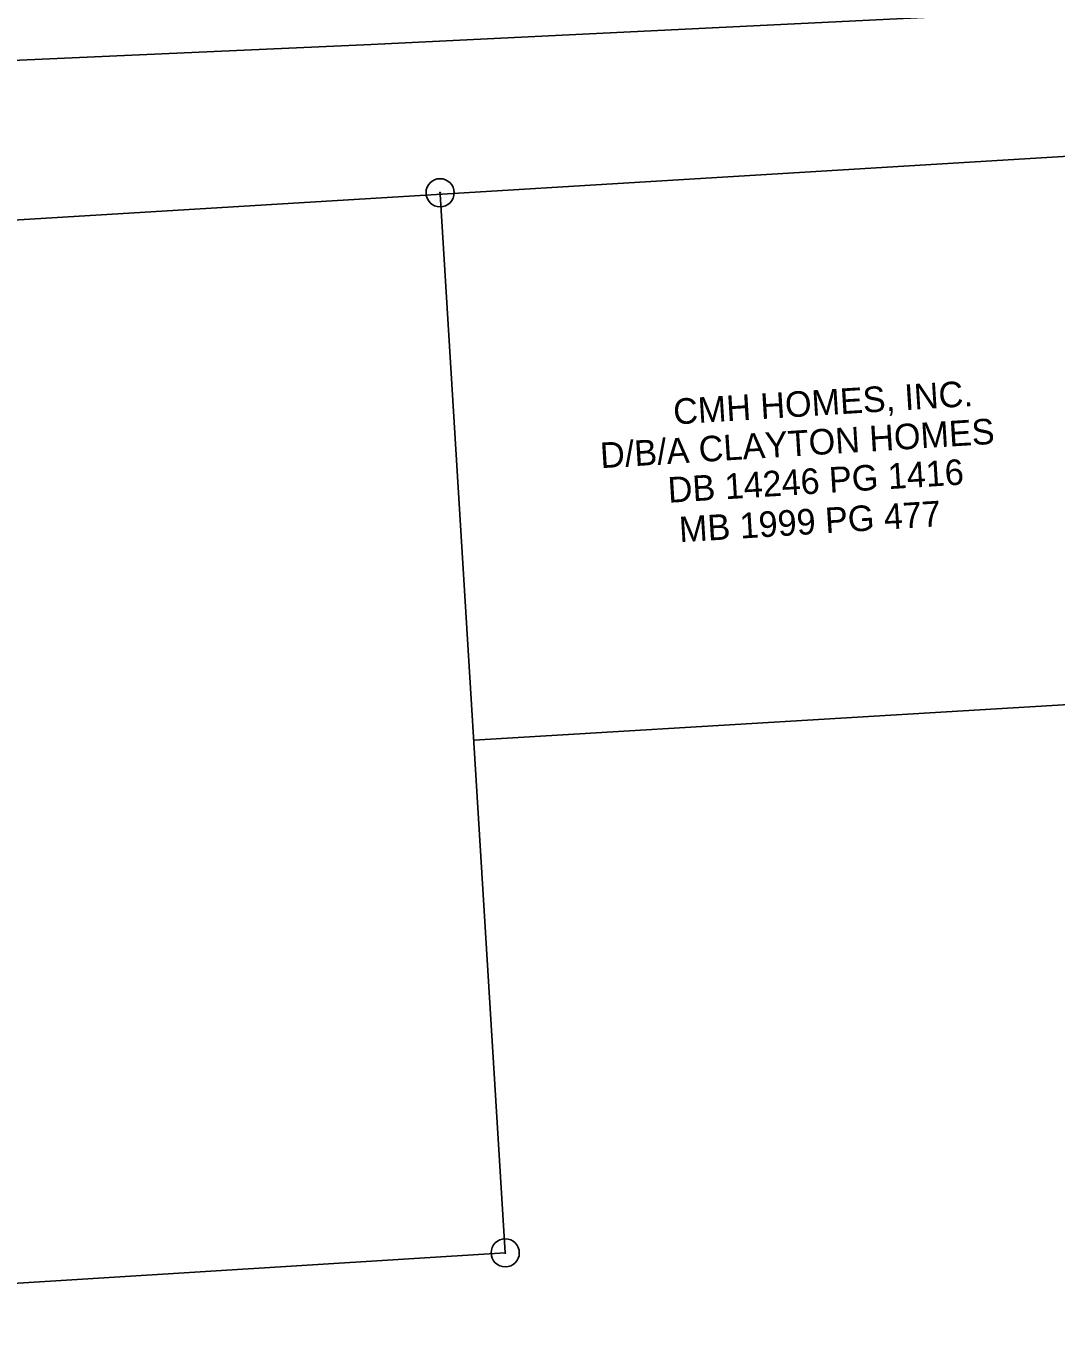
# Model space of a CAD drawing. Extents: x 2110969 to 2113691, y 670003 to 672285.
# Drawn here: x 2112326.2 to 2112487.4, y 670263.1 to 670466.5 of the extents above; entities that cross this region are included whole.
import ezdxf

# ---------------------------------------------------------------- set-up
doc = ezdxf.new("R2010")
doc.units = 0
for name, color, linetype in [('Exist Property Deed Book Text', 7, 'Continuous'), ('Exist Property Iron Pin CELL', 7, 'Continuous'), ('Exist Property Line', 7, 'Continuous'), ('Exist Property Owner Text', 7, 'Continuous'), ('Exist Right of Way Line', 7, 'Continuous'), ('Exist Utilities Telephone UG FO SUE LOS B', 7, 'Continuous')]:
    doc.layers.add(name, color=color, linetype=linetype)

msp = doc.modelspace()

# ---------------------------------------------------------------- linework, layer by layer
at = {"layer": 'Exist Property Iron Pin CELL'}
for centre, radius in [((2112391.04, 670440.42), 2.2), ((2112391.04, 670440.42), 0.0707), ((2112401.24, 670274.53), 2.2), ((2112401.24, 670274.53), 0.0707)]:
    msp.add_circle(centre, radius, dxfattribs=at)
at = {"layer": 'Exist Property Line'}
for p, q in [((2112401.24, 670274.53), (2112391.05, 670440.18)), ((2112495.74, 670360.7), (2112396.31, 670354.74)), ((2112401.24, 670274.53), (2112216.56, 670263.08))]:
    msp.add_line(p, q, dxfattribs=at)
at = {"layer": 'Exist Right of Way Line'}
msp.add_line((2112275.95, 670433.2), (2113479.86, 670506.17), dxfattribs=at)
at = {"layer": 'Exist Utilities Telephone UG FO SUE LOS B'}
msp.add_lwpolyline([(2111579.85, 670418.18), (2111631.45, 670423.41), (2111740.38, 670432.81), (2111885.62, 670444.53), (2111926.38, 670441.18), (2111977.11, 670441.9), (2112063.2, 670445.72), (2112109.68, 670453.08), (2112138.77, 670453.18), (2112237, 670457.87), (2112306.5, 670460.33), (2112380.27, 670463.6), (2112482.83, 670468.65), (2112529.94, 670475.11), (2112581.42, 670479.39), (2112613.55, 670486.14), (2112667.68, 670491.25), (2112816.71, 670501.11)], dxfattribs=at)
msp.add_lwpolyline([(2111579.85, 670418.18), (2111631.45, 670423.41), (2111740.38, 670432.81), (2111885.62, 670444.53), (2111926.38, 670441.18), (2111977.11, 670441.9), (2112063.2, 670445.72), (2112109.68, 670453.08), (2112138.77, 670453.18), (2112237, 670457.87), (2112306.5, 670460.33), (2112380.27, 670463.6), (2112482.83, 670468.65), (2112529.94, 670475.11), (2112581.42, 670479.39), (2112613.55, 670486.14), (2112667.68, 670491.25), (2112816.71, 670501.11)], dxfattribs=at)

# ---------------------------------------------------------------- texts
at = {"layer": 'Exist Property Deed Book Text'}
for s, p in [('DB 14246 PG 1416', (2112426.8, 670391.9)), ('MB 1999 PG 477', (2112428.56, 670385.71))]:
    msp.add_text(s, height=4, rotation=3.5509, dxfattribs=at).set_placement(p)
at = {"layer": 'Exist Property Owner Text'}
for s, p in [('CMH HOMES, INC.', (2112427.65, 670404.15)), ('D/B/A CLAYTON HOMES', (2112416.21, 670397.31))]:
    msp.add_text(s, height=4, rotation=3.5509, dxfattribs=at).set_placement(p)

doc.saveas('drawing.dxf')
